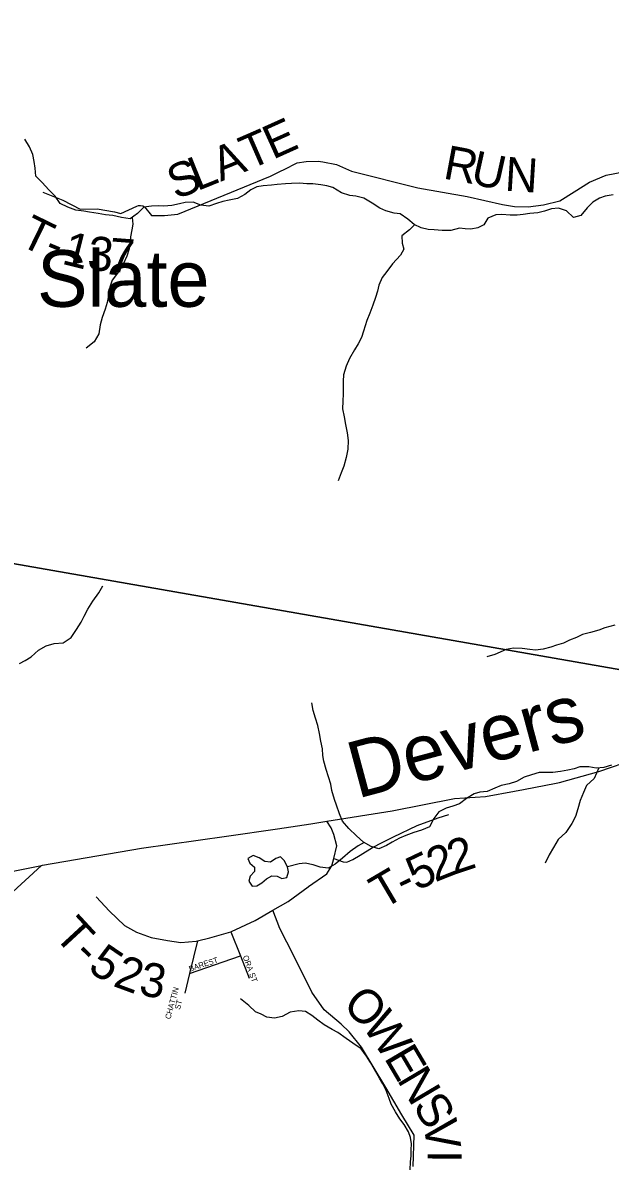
# Model space of a CAD drawing. Extents: x 1624196 to 2029251, y 146837 to 440034.
# Drawn here: x 1810588 to 1815776, y 316754 to 326836 of the extents above; entities that cross this region are included whole.
import ezdxf

# ---------------------------------------------------------------- set-up
doc = ezdxf.new("R2010")
doc.units = 0
for name, color, linetype in [('GM_X_County_Road', 7, 'Continuous'), ('GM_X_County_Road_Text', 7, 'Continuous'), ('GM_X_Minor_Lake', 7, 'Continuous'), ('GM_X_Minor_River', 7, 'Continuous'), ('GM_X_Minor_River_Text', 7, 'Continuous'), ('GM_X_State_Route', 7, 'Continuous'), ('GM_X_Township', 7, 'Continuous'), ('GM_X_Township_Road', 7, 'Continuous'), ('GM_X_Township_Road_Text', 7, 'Continuous'), ('GM_X_Township_Subdivision', 7, 'Continuous'), ('GM_X_Township_Subdivision_Text', 7, 'Continuous')]:
    doc.layers.add(name, color=color, linetype=linetype)

msp = doc.modelspace()

# ---------------------------------------------------------------- linework, layer by layer
at = {"layer": 'GM_X_County_Road'}
for points in [[(1813110, 319199), (1813111, 319199), (1813273, 319311), (1813316, 319383), (1813335, 319449), (1813361, 319559), (1813334, 319659), (1813311, 319719), (1813273, 319777)], [(1814036, 316725), (1814045, 317002), (1813935, 317182), (1813794, 317424), (1813579, 317781), (1813470, 317916), (1813400, 317984), (1813250, 318109), (1813140, 318267), (1812980, 318586), (1812859, 318830), (1812795, 318992), (1812931, 319068), (1813107, 319196), (1813110, 319199)]]:
    msp.add_lwpolyline(points, dxfattribs=at)
at = {"layer": 'GM_X_Minor_Lake'}
for points in [[(1812926, 319374), (1812895, 319430), (1812863, 319461), (1812821, 319447), (1812776, 319415), (1812726, 319420), (1812675, 319452), (1812621, 319475), (1812574, 319447), (1812592, 319405), (1812634, 319372), (1812635, 319346)], [(1812635, 319346), (1812635, 319332), (1812597, 319292), (1812585, 319248), (1812612, 319204), (1812656, 319206), (1812699, 319231), (1812741, 319267), (1812787, 319293), (1812833, 319292), (1812875, 319270), (1812919, 319280), (1812934, 319330), (1812926, 319374)]]:
    msp.add_lwpolyline(points, dxfattribs=at)
at = {"layer": 'GM_X_Minor_River'}
for points in [[(1813477, 325308), (1813403, 325333), (1813327, 325379), (1813273, 325394), (1813221, 325404), (1813149, 325413), (1813097, 325413), (1813031, 325418), (1812961, 325415), (1812909, 325411), (1812835, 325406), (1812783, 325400), (1812711, 325395), (1812654, 325385), (1812602, 325359), (1812548, 325318), (1812485, 325284), (1812409, 325269), (1812353, 325255), (1812297, 325238), (1812230, 325214), (1812160, 325225), (1812093, 325249), (1812023, 325246), (1811972, 325236), (1811904, 325221), (1811834, 325215), (1811784, 325218), (1811724, 325216), (1811656, 325207), (1811601, 325151), (1811535, 325102), (1811459, 325116), (1811383, 325133), (1811319, 325139), (1811253, 325150), (1811177, 325161), (1811125, 325171), (1811055, 325180), (1810985, 325206), (1810917, 325237), (1810872, 325303), (1810818, 325360), (1810759, 325424), (1810701, 325481), (1810696, 325551), (1810688, 325609), (1810677, 325672), (1810645, 325738), (1810606, 325807)], [(1815803, 325315), (1815733, 325302), (1815683, 325286), (1815622, 325250), (1815572, 325199), (1815517, 325133), (1815451, 325115), (1815389, 325174), (1815318, 325197), (1815257, 325191), (1815195, 325170), (1815137, 325156), (1815065, 325149), (1815007, 325141), (1814955, 325136), (1814891, 325134), (1814819, 325141), (1814767, 325139), (1814696, 325108), (1814660, 325050), (1814607, 325024), (1814545, 325013), (1814495, 325015), (1814445, 325020), (1814367, 325000), (1814293, 324999), (1814221, 325007), (1814169, 325010), (1814105, 325022), (1814043, 325053), (1813987, 325101), (1813920, 325146), (1813868, 325153), (1813794, 325173), (1813740, 325198), (1813674, 325240), (1813601, 325285), (1813529, 325304), (1813477, 325308)], [(1811553, 325115), (1811558, 325057), (1811550, 325007), (1811539, 324945), (1811535, 324895), (1811526, 324837), (1811506, 324773), (1811475, 324703), (1811433, 324633), (1811378, 324560), (1811355, 324500), (1811347, 324440), (1811332, 324362), (1811314, 324304), (1811287, 324230), (1811272, 324166), (1811260, 324086), (1811219, 324016), (1811148, 323958)], [(1814047, 325051), (1814003, 325005), (1813936, 324952), (1813937, 324889), (1813953, 324835), (1813924, 324781), (1813852, 324704), (1813803, 324636), (1813763, 324584), (1813732, 324516), (1813721, 324464), (1813703, 324408), (1813680, 324340), (1813652, 324270), (1813627, 324204), (1813598, 324111), (1813578, 324055), (1813551, 323999), (1813517, 323945), (1813474, 323869), (1813443, 323801), (1813419, 323723), (1813416, 323667), (1813416, 323609), (1813417, 323555), (1813415, 323491), (1813412, 323423), (1813425, 323352), (1813439, 323284), (1813452, 323210), (1813462, 323142), (1813459, 323067), (1813444, 322993), (1813422, 322917), (1813399, 322857), (1813372, 322788)], [(1810557, 321173), (1810608, 321199), (1810662, 321230), (1810725, 321290), (1810793, 321329), (1810865, 321349), (1810943, 321354), (1811014, 321402), (1811063, 321472), (1811103, 321537), (1811128, 321589), (1811162, 321651), (1811205, 321723), (1811260, 321795), (1811294, 321857)], [(1815818, 321511), (1815728, 321487), (1815677, 321466), (1815601, 321446), (1815531, 321427), (1815477, 321401), (1815418, 321378), (1815364, 321352), (1815302, 321335), (1815252, 321315), (1815183, 321297), (1815117, 321290), (1815065, 321296), (1814997, 321303), (1814921, 321308), (1814857, 321294), (1814756, 321251), (1814686, 321231)], [(1814812, 320092), (1814758, 320068), (1814690, 320041), (1814624, 320033), (1814574, 320018), (1814507, 319978), (1814445, 319931), (1814386, 319909), (1814328, 319892), (1814262, 319860), (1814217, 319802), (1814181, 319728), (1814108, 319697), (1814042, 319677), (1813970, 319650), (1813915, 319626), (1813849, 319591), (1813799, 319563), (1813732, 319534), (1813666, 319554), (1813597, 319593), (1813535, 319647), (1813468, 319714), (1813410, 319779), (1813385, 319841), (1813359, 319918), (1813340, 319970), (1813316, 320048), (1813309, 320104), (1813289, 320171), (1813268, 320235), (1813245, 320309), (1813237, 320359), (1813234, 320418), (1813220, 320486), (1813207, 320552), (1813193, 320622), (1813172, 320689), (1813152, 320757), (1813141, 320825)], [(1815787, 320274), (1815719, 320253), (1815651, 320247), (1815587, 320258), (1815509, 320257), (1815458, 320241), (1815402, 320229), (1815336, 320218), (1815270, 320208), (1815216, 320209), (1815150, 320207), (1815080, 320188), (1815015, 320166), (1814947, 320129), (1814883, 320107), (1814812, 320092)], [(1815676, 320249), (1815634, 320155), (1815567, 320092), (1815539, 320030), (1815512, 319960), (1815489, 319888), (1815469, 319818), (1815438, 319756), (1815383, 319676), (1815317, 319615), (1815274, 319545), (1815238, 319479), (1815201, 319407)], [(1813604, 319589), (1813550, 319559), (1813480, 319508), (1813411, 319450), (1813347, 319398), (1813284, 319363), (1813214, 319370), (1813151, 319392), (1813083, 319405), (1813030, 319401), (1812926, 319374)], [(1814009, 316696), (1814013, 316766), (1814017, 316818), (1814018, 316872), (1814022, 316924), (1814012, 316981), (1813993, 317031), (1813957, 317095), (1813919, 317146), (1813879, 317208), (1813842, 317275), (1813824, 317327), (1813796, 317397), (1813769, 317456), (1813737, 317506), (1813695, 317581), (1813659, 317645), (1813624, 317699), (1813576, 317764), (1813504, 317815), (1813444, 317855), (1813370, 317910), (1813320, 317936), (1813248, 317977), (1813192, 318019), (1813140, 318060), (1813084, 318094), (1813026, 318102), (1812948, 318089), (1812877, 318051), (1812811, 318035), (1812743, 318044), (1812693, 318070), (1812643, 318093), (1812583, 318147), (1812511, 318206)]]:
    msp.add_lwpolyline(points, dxfattribs=at)
at = {"layer": 'GM_X_State_Route'}
for points in [[(1815298, 320114), (1815328, 320120), (1815675, 320217), (1816002, 320330), (1816360, 320469), (1816594, 320536), (1816985, 320636), (1817739, 320751), (1817859, 320768), (1818372, 320839), (1818393, 320841), (1818628, 320869), (1818751, 320883), (1819439, 321014), (1820516, 321272)], [(1812836, 319711), (1813133, 319755), (1813273, 319777), (1813849, 319868), (1814402, 319978), (1814675, 319995), (1814932, 320043), (1815010, 320058), (1815298, 320114)], [(1810168, 319265), (1810237, 319282), (1810751, 319386), (1810762, 319388), (1811636, 319539), (1812388, 319644), (1812836, 319711)]]:
    msp.add_lwpolyline(points, dxfattribs=at)
at = {"layer": 'GM_X_Township'}
for points in [[(1821543, 327676), (1821586, 326586), (1821346, 325590), (1821296, 324784), (1821289, 324159), (1820889, 323104), (1820694, 322436), (1820969, 321781), (1821055, 321414), (1821100, 321222), (1821522, 320487), (1821671, 320101), (1821298, 320165), (1818633, 320632), (1817859, 320768), (1805881, 322864), (1805791, 322873), (1797487, 323721), (1796838, 323914), (1796776, 323969), (1795508, 325685), (1792128, 329660)], [(1805904, 298671), (1805039, 302173), (1804881, 302812), (1803628, 307887), (1802813, 311186), (1802585, 312112), (1800870, 319053), (1800824, 319242), (1800750, 319544), (1800213, 321753), (1800145, 321795), (1797270, 323640), (1796838, 323914), (1797487, 323721), (1805791, 322873), (1805881, 322864), (1817859, 320768), (1818633, 320632), (1821298, 320165), (1821671, 320101), (1822343, 318443)]]:
    msp.add_lwpolyline(points, dxfattribs=at)
at = {"layer": 'GM_X_Township_Road'}
for points in [[(1812864, 325524), (1812897, 325540), (1813011, 325599), (1813089, 325611), (1813197, 325614), (1813238, 325607), (1813357, 325582), (1813491, 325523), (1814076, 325377), (1814514, 325300), (1814824, 325231), (1814931, 325212), (1815052, 325209), (1815188, 325228), (1815332, 325263), (1815457, 325342), (1815592, 325427), (1815739, 325490), (1815907, 325520)], [(1810765, 325339), (1810940, 325268), (1811094, 325188), (1811244, 325191), (1811398, 325166), (1811454, 325149), (1811595, 325216), (1811609, 325221), (1811628, 325222), (1811648, 325217), (1811661, 325210), (1811724, 325131), (1811838, 325132), (1811958, 325145), (1812776, 325481), (1812858, 325521), (1812864, 325524)], [(1813763, 319589), (1813861, 319639), (1814072, 319740), (1814255, 319807), (1814350, 319838)], [(1813335, 319449), (1813417, 319419), (1813451, 319414), (1813503, 319439), (1813568, 319478), (1813676, 319545), (1813761, 319588), (1813763, 319589)], [(1809017, 318789), (1809018, 318790), (1809052, 318857), (1809074, 318876), (1809114, 318876), (1809616, 318863), (1810101, 318890), (1810183, 318907), (1810465, 319121), (1810751, 319386)], [(1811236, 319109), (1811353, 318982), (1811485, 318856), (1811593, 318795), (1811720, 318748), (1811865, 318722), (1811982, 318705), (1812118, 318716), (1812131, 318719), (1812239, 318746), (1812426, 318800), (1812431, 318802), (1812639, 318900), (1812795, 318992)]]:
    msp.add_lwpolyline(points, dxfattribs=at)
at = {"layer": 'GM_X_Township_Subdivision'}
for points in [[(1812426, 318800), (1812510, 318587), (1812588, 318390)], [(1812131, 318719), (1812061, 318432), (1812018, 318257)], [(1812061, 318432), (1812510, 318587)]]:
    msp.add_lwpolyline(points, dxfattribs=at)

# ---------------------------------------------------------------- texts
at = {"layer": 'GM_X_County_Road_Text'}
for s, rotation, p in [('O', 315.5487, (1813401, 318141)), ('W', 304.5564, (1813579, 317968)), ('E', 300.5029, (1813774, 317686)), ('N', 300.6649, (1813888, 317492)), ('S', 301.7409, (1814026, 317260)), ('V', 279.4228, (1814121, 317117)), ('I', 269.5941, (1814164, 316870))]:
    msp.add_text(s, height=300, rotation=rotation, dxfattribs=at).set_placement(p)
at = {"layer": 'GM_X_Minor_River_Text'}
for s, rotation, p in [('Slate', 0.005, (1810713, 324325)), ('Devers', 15.0018, (1813540, 319975))]:
    msp.add_text(s, height=500, rotation=rotation, dxfattribs=at).set_placement(p)
at = {"layer": 'GM_X_Township_Road_Text'}
for s, rotation, p in [('E', 24.2502, (1812796, 325624)), ('T', 23.5646, (1812587, 325533)), ('A', 22.149, (1812335, 325430)), ('R', 349.3736, (1814292, 325461)), ('U', 347.4898, (1814532, 325416)), ('S', 22.0767, (1811939, 325270)), ('L', 22.0773, (1812127, 325346)), ('N', 356.5017, (1814840, 325352)), ('T', 334.0329, (1810544, 324878)), ('1', 345.8904, (1810922, 324708)), ('3', 354.4694, (1811150, 324655)), ('-', 336.9746, (1810761, 324773)), ('7', 355.6626, (1811341, 324637)), ('2', 18.4415, (1814396, 319303)), ('5', 25.4712, (1814067, 319159)), ('2', 21.6768, (1814229, 319236)), ('T', 30.497, (1813769, 318993)), ('-', 26.3521, (1813957, 319105)), ('T', 312.7145, (1810853, 318762)), ('-', 315.9306, (1811018, 318584)), ('5', 326.0231, (1811151, 318462)), ('2', 339.8151, (1811375, 318323)), ('3', 349.8492, (1811603, 318244))]:
    msp.add_text(s, height=300, rotation=rotation, dxfattribs=at).set_placement(p)
at = {"layer": 'GM_X_Township_Subdivision_Text'}
for s, rotation, p in [('BARE', 18.9262, (1812064, 318446)), ('ST', 18.4393, (1812236, 318503)), ('ORA ST', 290.2843, (1812529, 318581)), ('CHATTIN', 74.8286, (1811891, 318023)), ('ST', 75.0622, (1811975, 318108))]:
    msp.add_text(s, height=50, rotation=rotation, dxfattribs=at).set_placement(p)

doc.saveas('drawing.dxf')
